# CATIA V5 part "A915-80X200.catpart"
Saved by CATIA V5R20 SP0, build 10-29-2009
Part number: A915-80X200
Source: Unknown
Property "A": "0.000"
Property "ARTICLENO": "A915-80X200"
Property "BOMINFO": "A915-80X200"
Property "CODE": "A915-80X200"
Property "CREATOR": "CADENAS GmbH"
Property "D": "13.500"
Property "D1": "20.000"
Property "FORM": "B"
Property "L": "200.000"
Property "L1": "25.000"
Property "L2": "150.000"
Property "LINA": "A915-80X200"
Property "NB": "A915-80X200"
Property "NBSYN": "$CODE."
Property "NN": "A915"
Property "NT": "VDI 3357 Wear Plates, steel"
Property "SCREW": "M12x25"
Property "SUPPLIER": "CF"
Property "T": "13.000"
Property "W": "80.000"
Bounding box of the stored display mesh (mm): x 0 to 20, y 0 to 200, z -40 to 40
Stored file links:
  C:\Users\borellobunino\Desktop\3D X SITO CF\A915\GSB_OILLESS_G22501080200\CATIAV5\A915-80X200.catpart
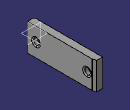
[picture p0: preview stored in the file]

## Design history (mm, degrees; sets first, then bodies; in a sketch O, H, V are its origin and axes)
Body1 "Geometry.1" (main body)
  Solid1 "A915-80X200.catpart": solid without history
